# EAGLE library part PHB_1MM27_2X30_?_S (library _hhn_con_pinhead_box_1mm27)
Pin Header Box-Type, 1.27mm/0.5"/50mil Pitch, 2x30 Circuits, single gates in schematic Note: see library description for an important note about THT-version
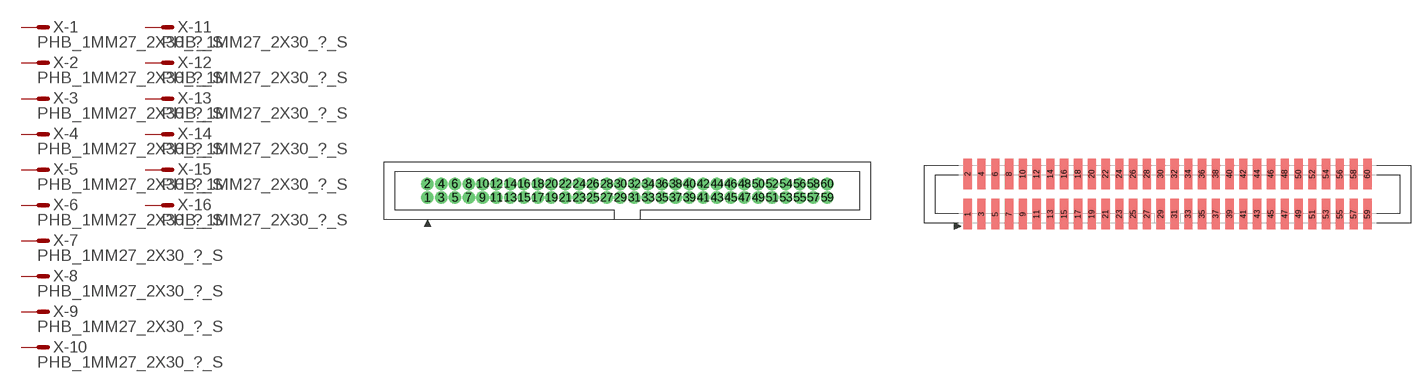
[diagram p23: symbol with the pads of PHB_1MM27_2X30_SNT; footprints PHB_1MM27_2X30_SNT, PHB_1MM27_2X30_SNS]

Designator prefix X; gates -1=M -2=M -3=M -4=M -5=M -6=M -7=M -8=M -9=M -10=M -11=M -12=M -13=M -14=M -15=M -16=M -17=M -18=M -19=M -20=M -21=M -22=M -23=M -24=M -25=M -26=M -27=M -28=M -29=M -30=M -31=M -32=M -33=M -34=M -35=M -36=M -37=M -38=M -39=M -40=M -41=M -42=M -43=M -44=M -45=M -46=M -47=M -48=M -49=M -50=M -51=M -52=M -53=M -54=M -55=M -56=M -57=M -58=M -59=M -60=M

## PHB_1MM27_2X30_SNT_S  [PHB_1MM27_2X30_SNT]
1  -1:S  pas
2  -2:S  pas
3  -3:S  pas
4  -4:S  pas
5  -5:S  pas
6  -6:S  pas
7  -7:S  pas
8  -8:S  pas
9  -9:S  pas
10  -10:S  pas
11  -11:S  pas
12  -12:S  pas
13  -13:S  pas
14  -14:S  pas
15  -15:S  pas
16  -16:S  pas
17  -17:S  pas
18  -18:S  pas
19  -19:S  pas
20  -20:S  pas
21  -21:S  pas
22  -22:S  pas
23  -23:S  pas
24  -24:S  pas
25  -25:S  pas
26  -26:S  pas
27  -27:S  pas
28  -28:S  pas
29  -29:S  pas
30  -30:S  pas
31  -31:S  pas
32  -32:S  pas
33  -33:S  pas
34  -34:S  pas
35  -35:S  pas
36  -36:S  pas
37  -37:S  pas
38  -38:S  pas
39  -39:S  pas
40  -40:S  pas
41  -41:S  pas
42  -42:S  pas
43  -43:S  pas
44  -44:S  pas
45  -45:S  pas
46  -46:S  pas
47  -47:S  pas
48  -48:S  pas
49  -49:S  pas
50  -50:S  pas
51  -51:S  pas
52  -52:S  pas
53  -53:S  pas
54  -54:S  pas
55  -55:S  pas
56  -56:S  pas
57  -57:S  pas
58  -58:S  pas
59  -59:S  pas
60  -60:S  pas

## PHB_1MM27_2X30_SNS_S  [PHB_1MM27_2X30_SNS]
Pads as for PHB_1MM27_2X30_SNT

## Footprint PHB_1MM27_2X30_SNT (pad centres in mm)
Pin Header Box-Type, 1.27mm Pitch, 2x30 circuits, Straight, No Locking, THT Important Note: Diameter in this lbr is set to a specific value (NOT 'auto' = 0), this is ignored by actual eagle versions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
drill 0.65 pad 1 round: 1 -18.415,-0.635; 2 -18.415,0.635; 3 -17.145,-0.635; 4 -17.145,0.635; 5 -15.875,-0.635; 6 -15.875,0.635; 7 -14.605,-0.635; 8 -14.605,0.635; 9 -13.335,-0.635; 10 -13.335,0.635; 11 -12.065,-0.635; 12 -12.065,0.635; 13 -10.795,-0.635; 14 -10.795,0.635; 15 -9.525,-0.635; 16 -9.525,0.635; 17 -8.255,-0.635; 18 -8.255,0.635; 19 -6.985,-0.635; 20 -6.985,0.635; 21 -5.715,-0.635; 22 -5.715,0.635; 23 -4.445,-0.635; 24 -4.445,0.635; 25 -3.175,-0.635; 26 -3.175,0.635; 27 -1.905,-0.635; 28 -1.905,0.635; 29 -0.635,-0.635; 30 -0.635,0.635; 31 0.635,-0.635; 32 0.635,0.635; 33 1.905,-0.635; 34 1.905,0.635; 35 3.175,-0.635; 36 3.175,0.635; 37 4.445,-0.635; 38 4.445,0.635; 39 5.715,-0.635; 40 5.715,0.635; 41 6.985,-0.635; 42 6.985,0.635; 43 8.255,-0.635; 44 8.255,0.635; 45 9.525,-0.635; 46 9.525,0.635; 47 10.795,-0.635; 48 10.795,0.635; 49 12.065,-0.635; 50 12.065,0.635; 51 13.335,-0.635; 52 13.335,0.635; 53 14.605,-0.635; 54 14.605,0.635; 55 15.875,-0.635; 56 15.875,0.635; 57 17.145,-0.635; 58 17.145,0.635; 59 18.415,-0.635; 60 18.415,0.635

## Footprint PHB_1MM27_2X30_SNS (pad centres in mm)
Pin Header Box-Type, 1.27mm Pitch, 2x30 circuits, Straight, No Locking, SMT
smd 0.76 x 2.8: 1 -18.415,-1.85; 2 -18.415,1.85; 3 -17.145,-1.85; 4 -17.145,1.85; 5 -15.875,-1.85; 6 -15.875,1.85; 7 -14.605,-1.85; 8 -14.605,1.85; 9 -13.335,-1.85; 10 -13.335,1.85; 11 -12.065,-1.85; 12 -12.065,1.85; 13 -10.795,-1.85; 14 -10.795,1.85; 15 -9.525,-1.85; 16 -9.525,1.85; 17 -8.255,-1.85; 18 -8.255,1.85; 19 -6.985,-1.85; 20 -6.985,1.85; 21 -5.715,-1.85; 22 -5.715,1.85; 23 -4.445,-1.85; 24 -4.445,1.85; 25 -3.175,-1.85; 26 -3.175,1.85; 27 -1.905,-1.85; 28 -1.905,1.85; 29 -0.635,-1.85; 30 -0.635,1.85; 31 0.635,-1.85; 32 0.635,1.85; 33 1.905,-1.85; 34 1.905,1.85; 35 3.175,-1.85; 36 3.175,1.85; 37 4.445,-1.85; 38 4.445,1.85; 39 5.715,-1.85; 40 5.715,1.85; 41 6.985,-1.85; 42 6.985,1.85; 43 8.255,-1.85; 44 8.255,1.85; 45 9.525,-1.85; 46 9.525,1.85; 47 10.795,-1.85; 48 10.795,1.85; 49 12.065,-1.85; 50 12.065,1.85; 51 13.335,-1.85; 52 13.335,1.85; 53 14.605,-1.85; 54 14.605,1.85; 55 15.875,-1.85; 56 15.875,1.85; 57 17.145,-1.85; 58 17.145,1.85; 59 18.415,-1.85; 60 18.415,1.85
